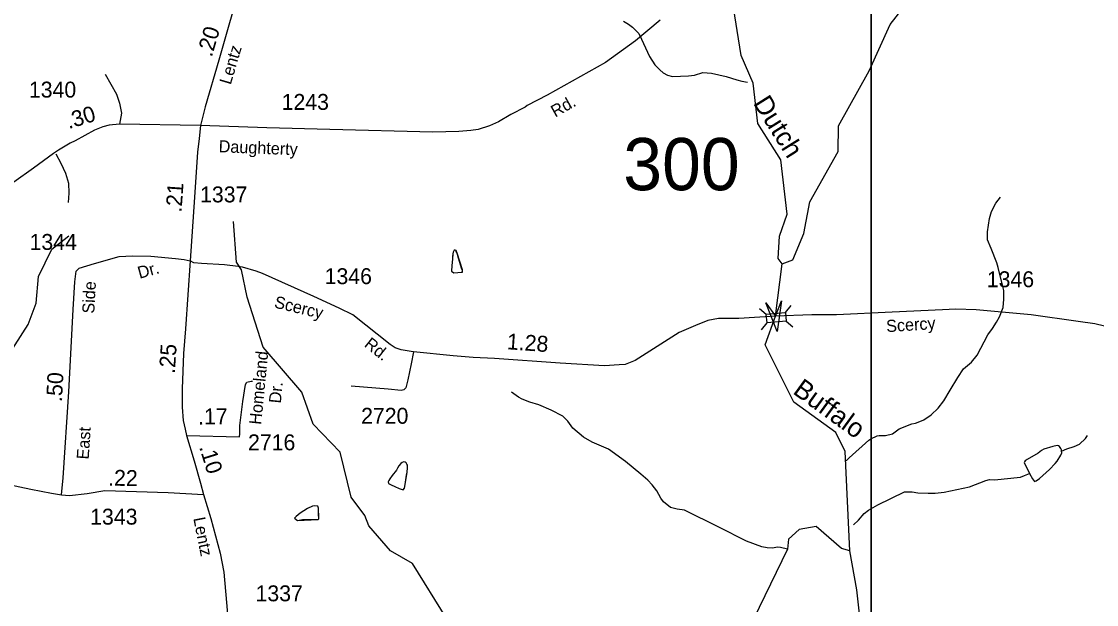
# Model space of a CAD drawing. Extents: x 1473865 to 1648260, y 639067 to 773536.
# Drawn here: x 1537453 to 1545902, y 653093 to 657671 of the extents above; entities that cross this region are included whole.
import ezdxf

# ---------------------------------------------------------------- set-up
doc = ezdxf.new("R2010")
doc.units = 0
for name, color, linetype in [('Exist Hydrographic Creek Single Shore', 7, 'Continuous'), ('Exist Hydrographic Creek Single Shore Label', 7, 'Continuous'), ('Exist Hydrographic Misc Water Feature', 7, 'Continuous'), ('Exist Road Non-System Type 51', 7, 'Continuous'), ('Exist Road Secondary Mileage Hundredths English Label', 7, 'Continuous'), ('Exist Road Secondary Structure Standard Bridge Attributed CELL', 7, 'Continuous'), ('Exist Road Secondary Structure Standard Bridge CELL', 7, 'Continuous'), ('Exist Road Secondary Structure Standard Bridge Number Label', 7, 'Continuous'), ('Exist Road Secondary Type 51 Attributed', 7, 'Continuous'), ('Exist Road Secondary Type 51 Label', 7, 'Continuous'), ('Exist Road Secondary Type 51 Number Label', 7, 'Continuous'), ('Map Preparation Inset Cut Line', 7, 'Continuous')]:
    doc.layers.add(name, color=color, linetype=linetype)

msp = doc.modelspace()

# ---------------------------------------------------------------- linework, layer by layer
at = {"layer": 'Exist Hydrographic Creek Single Shore'}
for points in [[(1543432.1, 655767.4), (1543399.1, 655810.7), (1543410.1, 655984.4), (1543471.1, 656157.2), (1543420.2, 656584.9), (1543241.2, 656870.8), (1543204.1, 657186.7), (1543108.1, 657405.3), (1543039.1, 657849.8), (1543053.1, 658158), (1543225.2, 658512.4), (1543248.1, 659421.2), (1543300.1, 659587.5), (1543327.2, 659705.1), (1543446.1, 659860.3), (1543827.2, 660180.9), (1544006.2, 660485.8), (1544207.2, 661049.6), (1544374.2, 661581.3), (1544698.1, 662057.2), (1545054.2, 662437.4)], [(1536274, 652777), (1536354, 653110.2), (1536368, 653467.7), (1536548, 653782.5), (1536591, 653883.4), (1536999.1, 654360.9), (1537281, 654772.2), (1537343, 655036.7), (1537505, 655292.8), (1537567.1, 655459), (1537587, 655668.6), (1537690.1, 655883.2), (1537825, 655988.7)], [(1543963, 653514.7), (1543926.1, 654293.4), (1543853.1, 654442.6), (1543523.1, 654682.3), (1543298.1, 655131.4), (1543377.7, 655357.4), (1543432.1, 655767.4)], [(1544075.1, 652688.5), (1544017.1, 653208.4), (1543963, 653514.7)]]:
    msp.add_lwpolyline(points, dxfattribs=at)
at = {"layer": 'Exist Hydrographic Misc Water Feature'}
for points in [[(1543432.1, 655767.4), (1543516.1, 655798.5), (1543602.1, 656006.8), (1543648.1, 656255.4), (1543871.1, 656651.3), (1543874.1, 656851.4), (1544114.2, 657283.2), (1544279.1, 657647.6), (1544517.1, 657951.2), (1544697.1, 658282.4), (1544905.1, 658803.4), (1545219.2, 659131.9), (1545484.2, 659536.9), (1545535.2, 659644.1), (1545571.2, 659761.6), (1546156.2, 660944.6), (1546335.2, 661180.7), (1546530.2, 661386.8), (1546559.2, 661635.7), (1546602.2, 661726.7), (1546837.3, 661856.5)], [(1542183.2, 657672.6), (1542222.8, 657651.2), (1542254.5, 657626.8), (1542305.8, 657578.1), (1542325, 657531.8), (1542389, 657396.8), (1542431.9, 657331.9), (1542469.3, 657291.7), (1542496.9, 657269), (1542530.6, 657250.3), (1542570.6, 657239.7), (1542694.6, 657243.7), (1542742.8, 657250.9), (1542807.2, 657270.2), (1542875.1, 657265.5), (1542990.8, 657239.4), (1543074.3, 657212.3), (1543114.1, 657201.6), (1543160.2, 657195)], [(1543933.6, 654221), (1543957.9, 654245.2), (1544112.2, 654382.4), (1544128.3, 654394.4), (1544178.6, 654417.1), (1544194.8, 654420.9), (1544242.9, 654420.8), (1544298.9, 654431.9), (1544351.6, 654471.1), (1544450.2, 654511), (1544480.4, 654516.9), (1544512.6, 654528.6), (1544544.9, 654541.9), (1544601.5, 654582.6), (1544656.3, 654635.6), (1544703.2, 654691.3), (1544752.7, 654774.8), (1544812.2, 654875.4), (1544857.2, 654943.4), (1544920.2, 654996.3), (1544965, 655051.2), (1545047.7, 655210.4), (1545084.4, 655261.3), (1545117.2, 655309.1), (1545139.7, 655352.9), (1545167.1, 655426.2), (1545174.1, 655490.1), (1545173, 655558.2), (1545165.7, 655590.4), (1545127.8, 655738.9), (1545118.5, 655775.2), (1545074.2, 655887.6), (1545045.3, 655956.3), (1545046.3, 656020.4), (1545060, 656124.3), (1545076.9, 656179.7), (1545110, 656243.9), (1545146.6, 656290.8)], [(1540795.1, 652981.2), (1540527.1, 653413.3), (1540354, 653515.3), (1540182.1, 653709.2), (1540150.1, 653791.9), (1540043.1, 653935.1), (1539957, 654288.1), (1539744.1, 654509), (1539656, 654760.3), (1539353.1, 655114.3), (1539226, 655507.5), (1539181.6, 655720.5), (1539142.9, 655782), (1539119.1, 656100.5)], [(1540839.3, 655804.9), (1540834.4, 655754.9), (1540833.7, 655710.6), (1540851.5, 655697.9), (1540881.7, 655699.8), (1540907.6, 655701.7), (1540917.7, 655703.1), (1540917.8, 655711.3), (1540918, 655719.6), (1540912.2, 655733.6), (1540894.9, 655787.3), (1540881.7, 655831.9), (1540876, 655851.7), (1540870.2, 655864.2), (1540868.4, 655872.4), (1540862.5, 655876.6), (1540852.4, 655874.4), (1540846.1, 655860.5), (1540843.9, 655846.6), (1540841.5, 655824.5), (1540839.3, 655804.9)], [(1540839.3, 655804.9), (1540834.4, 655754.9), (1540833.7, 655710.6), (1540851.5, 655697.9), (1540881.7, 655699.8), (1540907.6, 655701.7), (1540917.7, 655703.1), (1540918, 655719.6), (1540876, 655851.7), (1540868.4, 655872.4), (1540862.5, 655876.6), (1540852.4, 655874.4), (1540846.1, 655860.5), (1540843.9, 655846.6), (1540839.3, 655804.9)], [(1543472.3, 653527.9), (1543418.7, 653541.3), (1543394.7, 653541.7), (1543354.5, 653536), (1543314.6, 653536.8), (1543270.7, 653545.1), (1543151.3, 653589.4), (1542934.9, 653700.4), (1542665, 653833), (1542605, 653841.6), (1542553.1, 653855), (1542497.8, 653899.6), (1542478.3, 653927.9), (1542447.2, 653984.3), (1542410.1, 654033.5), (1542374.5, 654069.5), (1542321.2, 654114.9), (1542200.8, 654216.6), (1542066.3, 654312.8), (1541939, 654366.3), (1541869.7, 654407.9), (1541786.7, 654476.9), (1541747.7, 654531.8), (1541708.2, 654570.4), (1541616.8, 654618.2), (1541519.4, 654661.2), (1541447.9, 654682.3), (1541388.2, 654705.7), (1541360.4, 654720.2), (1541305, 654759)], [(1545627.4, 654296.8), (1545669.7, 654315.7), (1545726, 654333.4), (1545768.4, 654352.3), (1545815.1, 654395.6), (1545831.4, 654419.1)], [(1545376.5, 654122.2), (1545398, 654078.3), (1545413.6, 654058.2), (1545427.6, 654063.7), (1545454, 654081.2), (1545480.3, 654104.5), (1545531.2, 654151.9), (1545577.9, 654201), (1545592.2, 654218.8), (1545622.8, 654264.9), (1545629.2, 654284.5), (1545627.4, 654296.8)], [(1545627.4, 654296.8), (1545625.6, 654306.7), (1545621.6, 654316.6), (1545615.9, 654326.6), (1545609.9, 654333.3), (1545602, 654339.2), (1545592, 654341), (1545558, 654333.5), (1545487.6, 654312.8), (1545469.4, 654300.8), (1545443.1, 654281.7)], [(1540399, 654147.1), (1540366.3, 654105.1), (1540347.8, 654079.2), (1540339.8, 654065.4), (1540335.5, 654055.7), (1540337.2, 654044.1), (1540359.1, 654033), (1540387, 654019.3), (1540420.8, 654004.6), (1540452.5, 653994.2), (1540462.8, 654005.5), (1540469.2, 654035.7), (1540473.8, 654071.7), (1540478.5, 654107.7), (1540482.9, 654133.1), (1540487.4, 654165.8), (1540485.6, 654187.2), (1540481.9, 654195.5), (1540475.9, 654205.4), (1540468, 654211.3), (1540458, 654214), (1540446, 654208.5), (1540433.8, 654200.5), (1540419.6, 654180.3), (1540407.1, 654162.5), (1540399, 654147.1)], [(1540399, 654147.1), (1540366.3, 654105.1), (1540347.8, 654079.2), (1540339.8, 654065.4), (1540335.5, 654055.7), (1540337.2, 654044.1), (1540359.1, 654033), (1540387, 654019.3), (1540420.8, 654004.6), (1540452.5, 653994.2), (1540462.8, 654005.5), (1540469.2, 654035.7), (1540482.9, 654133.1), (1540487.4, 654165.8), (1540485.6, 654187.2), (1540481.9, 654195.5), (1540475.9, 654205.4), (1540468, 654211.3), (1540458, 654214), (1540446, 654208.5), (1540433.8, 654200.5), (1540419.6, 654180.3), (1540407.1, 654162.5), (1540399, 654147.1)], [(1545443.1, 654281.7), (1545358.1, 654230.9), (1545342.1, 654221.3), (1545336.1, 654213.2), (1545333.8, 654205.1), (1545364.8, 654144.5), (1545376.5, 654122.2)], [(1543991.5, 653718.4), (1544030.2, 653753.8), (1544077, 653807), (1544109.6, 653834.3), (1544182.2, 653875.5), (1544394, 653977.9), (1544453.8, 653976.7), (1544497.8, 653970), (1544577.8, 653966.8), (1544633.8, 653966.5), (1544705.9, 653974.9), (1544902.7, 654016), (1545031.5, 654066), (1545061.6, 654073.5), (1545103.6, 654072.7), (1545175.8, 654079.4), (1545304.1, 654093.3), (1545336.3, 654104.9), (1545376.5, 654122.2)], [(1539788.1, 653850), (1539782.1, 653864.1), (1539756.4, 653868.7), (1539740.3, 653865), (1539699.9, 653846), (1539643.4, 653810.3), (1539610.9, 653784.7), (1539598.7, 653769.4), (1539622.4, 653753.3), (1539662.5, 653759.8), (1539782.5, 653760.7), (1539788.8, 653766.3), (1539790.8, 653776.1), (1539787, 653792.6), (1539788.1, 653850)], [(1539788.1, 653850), (1539782.1, 653864.1), (1539756.4, 653868.7), (1539740.3, 653865), (1539699.9, 653846), (1539643.4, 653810.3), (1539610.9, 653784.7), (1539598.7, 653769.4), (1539622.4, 653753.3), (1539782.5, 653760.7), (1539788.8, 653766.3), (1539790.8, 653776.1), (1539788.1, 653850)], [(1543963, 653514.7), (1543897.1, 653532.5), (1543699, 653703.9), (1543566.1, 653680.3), (1543481.1, 653606.5), (1543472.3, 653527.9), (1543205.1, 652978.5)]]:
    msp.add_lwpolyline(points, dxfattribs=at)
at = {"layer": 'Exist Road Non-System Type 51'}
for points in [[(1538111.4, 657257.1), (1538198.5, 657099.4), (1538223.3, 657030.9), (1538237.7, 656950.8), (1538222.4, 656865.8)], [(1537722.2, 656631.4), (1537762.4, 656559.8), (1537799, 656479.2), (1537821.4, 656402.7), (1537826, 656322.8), (1537820.5, 656248.8)]]:
    msp.add_lwpolyline(points, dxfattribs=at)
at = {"layer": 'Exist Road Secondary Structure Standard Bridge Attributed CELL'}
msp.add_lwpolyline([(1543427, 655477.7), (1543392, 655236.4), (1543301.7, 655462.9), (1543377.7, 655357.4)], close=True, dxfattribs=at)
at = {"layer": 'Exist Road Secondary Structure Standard Bridge CELL'}
for p, q in [((1543253.7, 655418.1), (1543306.6, 655373.8)), ((1543457.1, 655386.7), (1543501.4, 655439.6)), ((1543268.5, 655250.6), (1543312.8, 655303.5)), ((1543463.2, 655318), (1543516.1, 655273.7))]:
    msp.add_line(p, q, dxfattribs=at)
msp.add_lwpolyline([(1543306.6, 655373.8), (1543457.1, 655387.1), (1543463.3, 655316.8), (1543312.8, 655303.5)], close=True, dxfattribs=at)
at = {"layer": 'Exist Road Secondary Type 51 Attributed'}
for points in [[(1539150.4, 657879.4), (1539076.5, 657623.6), (1539002.8, 657368.2), (1538895.8, 657002.3), (1538860.1, 656854.5)], [(1542472.7, 657681.1), (1542277.7, 657519), (1542042.6, 657349.4), (1541583.8, 657092.2), (1541428.5, 657011.1), (1541410.2, 656997.4), (1541299.2, 656939.6), (1541202, 656883.4), (1541131.5, 656852.8), (1541042.9, 656822.5), (1540984.9, 656815.5), (1540890.7, 656807.4), (1540684.7, 656803.2), (1539875.1, 656822.5), (1539380.6, 656835.9), (1538860.1, 656854.5)], [(1538860.1, 656854.5), (1538222.4, 656865.8), (1538142.7, 656857.1), (1538091.8, 656842.7), (1538026.4, 656817.2), (1537874.4, 656734.8), (1537835.4, 656714.5), (1537743.7, 656660.1), (1537704.6, 656634.6), (1537546.1, 656518.7), (1537393.9, 656408.8)], [(1538860.1, 656854.5), (1538848.2, 656751.8), (1538837.2, 656644.8), (1538813.5, 656290.8), (1538777.7, 655790.8)], [(1537767.6, 653954.6), (1537780.1, 654088.2), (1537824.7, 654763.2), (1537858.8, 655410.2), (1537873, 655626.1), (1537882.5, 655709.7), (1537907, 655733.2), (1538027.6, 655771), (1538220.6, 655825.4), (1538324.8, 655831.5), (1538468.8, 655828.8), (1538664.3, 655809.3), (1538732, 655803.1), (1538777.7, 655790.8)], [(1538777.7, 655790.8), (1538742.1, 655257.6), (1538726.5, 655064.8), (1538715.7, 654785.7), (1538714.8, 654641.6), (1538724.5, 654537), (1538738.6, 654469.3), (1538749.1, 654420.9)], [(1540534.2, 655076.4), (1540514.4, 655078.3), (1540436.6, 655091.7), (1540389.8, 655109.5), (1540349.5, 655135.5), (1540058, 655366.9), (1539948.8, 655420.9), (1539750.6, 655512.6), (1539346.4, 655691.5), (1539296.3, 655711.7), (1539190.8, 655741.6), (1539156.9, 655747.8), (1539048.4, 655760.1), (1538867.3, 655771.5), (1538806.7, 655776.8), (1538777.7, 655790.8)], [(1546895.8, 655244), (1546791.1, 655242.1), (1546633.3, 655245.1), (1546418, 655225.1), (1546326.8, 655229.6), (1546290.6, 655228.8), (1546183.4, 655230.8), (1546031.2, 655261.8), (1545889, 655296.7), (1545758.9, 655316.4), (1545388.1, 655366.5), (1544955.2, 655407.5), (1544797.3, 655412.2), (1544692.5, 655407.6), (1544296, 655389.4), (1543858.6, 655366.6), (1543767.9, 655366.6), (1543663.9, 655366.5), (1543377.7, 655357.4)], [(1543377.7, 655357.4), (1543091.1, 655337.7), (1542931.7, 655339.4), (1542845.9, 655323.3), (1542749.2, 655283.2), (1542622.2, 655228.1), (1542275.1, 655009.2), (1542198.4, 654978.5), (1542150.5, 654975.5), (1542034.3, 654967.6), (1541686.7, 654988.3), (1541171.4, 655024.1), (1541003.5, 655033.1), (1540845.9, 655046), (1540534.2, 655076.4)], [(1540534.2, 655076.4), (1540516, 654982.5), (1540489.6, 654857.1), (1540474.3, 654793.3), (1540458.9, 654777.9), (1540436.9, 654773.5), (1540333.5, 654784.5), (1540043.1, 654807.8)], [(1538749.1, 654420.9), (1539166.6, 654408.6), (1539169.3, 654432.4), (1539169.3, 654498.3), (1539191.2, 654686.4), (1539212.3, 654820), (1539222.9, 654839.3), (1539258.3, 654846.1), (1539269.1, 654846.8)], [(1537022.1, 654510.5), (1537060, 654395.6), (1537095.3, 654253.1), (1537119.4, 654166.5), (1537144.8, 654129.4), (1537179, 654102), (1537225, 654075.6), (1537354.1, 654035.5), (1537526.6, 653999), (1537687.8, 653966), (1537767.6, 653954.6)], [(1538749.1, 654420.9), (1538808.9, 654219.7), (1538859, 654046.5), (1538883.6, 653957.7)], [(1537767.6, 653954.6), (1537829.3, 653947.5), (1537969.9, 653964.7), (1538108.2, 653988.1), (1538604.9, 653971.8), (1538883.6, 653957.7)], [(1538883.6, 653957.7), (1538940.7, 653767), (1539014.6, 653495.4), (1539042.7, 653346), (1539062.9, 653107.8), (1539079.6, 652926.7), (1539104.2, 652599.7), (1539113, 652511.8), (1539123.5, 652445), (1539135, 652409), (1539164, 652331.6), (1539215, 652214.7), (1539256.3, 652140.9), (1539319.6, 652018.7)]]:
    msp.add_lwpolyline(points, dxfattribs=at)
at = {"layer": 'Map Preparation Inset Cut Line'}
for points in [[(1481537.9, 640573), (1544130.8, 640573), (1544130.8, 678673.7), (1481537.9, 678673.7), (1481537.9, 640573)], [(1544130.8, 639067.3), (1606587.1, 639067.3), (1606587.1, 678673.7), (1544130.8, 678673.7), (1544130.8, 639067.3)]]:
    msp.add_lwpolyline(points, dxfattribs=at)

# ---------------------------------------------------------------- texts
at = {"layer": 'Exist Hydrographic Creek Single Shore Label'}
for s, rotation, p in [('Dutch', 302.05249, (1543199.8, 657029.5)), ('Buffalo', 324.00863, (1543507.5, 654754.5))]:
    msp.add_text(s, height=150, rotation=rotation, dxfattribs=at).set_placement(p)
at = {"layer": 'Exist Road Secondary Mileage Hundredths English Label'}
for s, rotation, p in [('.20', 73.53135, (1538948.3, 657386.7)), ('.30', 17.04846, (1537824.2, 656825.9)), ('.21', 85.96735, (1538710.3, 656169.8)), ('1.28', 356.02488, (1541265, 655097.4)), ('.25', 86.16249, (1538657.5, 654903.3)), ('.50', 86.98515, (1537771.1, 654681.3)), ('.17', 0.81061, (1538841.8, 654505.8)), ('.10', 287.34682, (1538848.3, 654329.2)), ('.22', 359.17033, (1538133.1, 654025.9))]:
    msp.add_text(s, height=125, rotation=rotation, dxfattribs=at).set_placement(p)
at = {"layer": 'Exist Road Secondary Structure Standard Bridge Number Label'}
msp.add_text('300', height=410.1, dxfattribs=at).set_placement((1542182.5, 656346.1))
at = {"layer": 'Exist Road Secondary Type 51 Label'}
for s, rotation, p in [('Lentz', 73.53135, (1539097, 657169.9)), ('Rd.', 29.28146, (1541647.3, 656916.2)), ('Daughterty', 357.7666, (1539001.4, 656644.8)), ('Dr.', 15.72376, (1538381, 655650.1)), ('Side', 86.98512, (1538024.7, 655375.3)), ('Scercy', 346.40718, (1539433.7, 655425.7)), ('Scercy', 3.67461, (1544251.8, 655231.1)), ('Rd.', 321.55476, (1540140.3, 655123.7)), ('Homeland', 84.46311, (1539336.8, 654501.7)), ('Dr.', 84.46311, (1539491, 654669.2)), ('East', 86.21607, (1537980.8, 654229.6)), ('Lentz', 281.25794, (1538802.7, 653769.5))]:
    msp.add_text(s, height=95, rotation=rotation, dxfattribs=at).set_placement(p)
at = {"layer": 'Exist Road Secondary Type 51 Number Label'}
for s, p in [('1340', (1537511.1, 657073.8)), ('1243', (1539497.5, 656977.2)), ('1337', (1538856.4, 656250.5)), ('1344', (1537516.2, 655877.4)), ('1346', (1539835.4, 655608.5)), ('1346', (1545039.7, 655584.3)), ('2720', (1540121.9, 654512)), ('2716', (1539233.4, 654303.6)), ('1343', (1537992.5, 653719.8)), ('1337', (1539292.3, 653117.7))]:
    msp.add_text(s, height=125, dxfattribs=at).set_placement(p)

doc.saveas('drawing.dxf')
